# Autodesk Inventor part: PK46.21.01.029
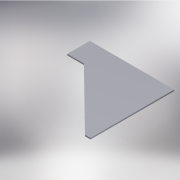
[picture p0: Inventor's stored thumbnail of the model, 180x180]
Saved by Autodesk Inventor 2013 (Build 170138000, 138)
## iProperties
Created: 2005-04
Part Number: PK46.21.01.029
Material: Steel, Mild
Document SubType Name: Modeling
Designer: salex
Manufacturer: Standard
Standards Organization: Custom
Density: 7.86 g/cm^3
Author: salex
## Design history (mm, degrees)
sketch "Эскиз1"
  geometry: L1 (0, 0)-(0, 163); L2 (0, 163)-(610, 163); L3 (610, 163)-(610, -442); L4 (610, -442)-(570, -442); L5 (570, -442)-(120, 0); L6 (120, 0)-(0, 0)
  constraints: 12 end point, 3 parallel, 1 perpendicular, 1 vertical, 1 other
  dimensions: "d0" = 610 distance between parallel lines of L3 L1; "d3" = 605 distance between parallel lines of L2 L4; "d7" = 40 distance of L3.end L4.end; "d8" = 490 distance from line of L5.end L3; "d9" = 442 distance between parallel lines of L6 L4
extrude "Выдавливание1" new body sketch "Эскиз1" distance "d5" = 10; taper "d6" = 0 deg
body "Solid1"
